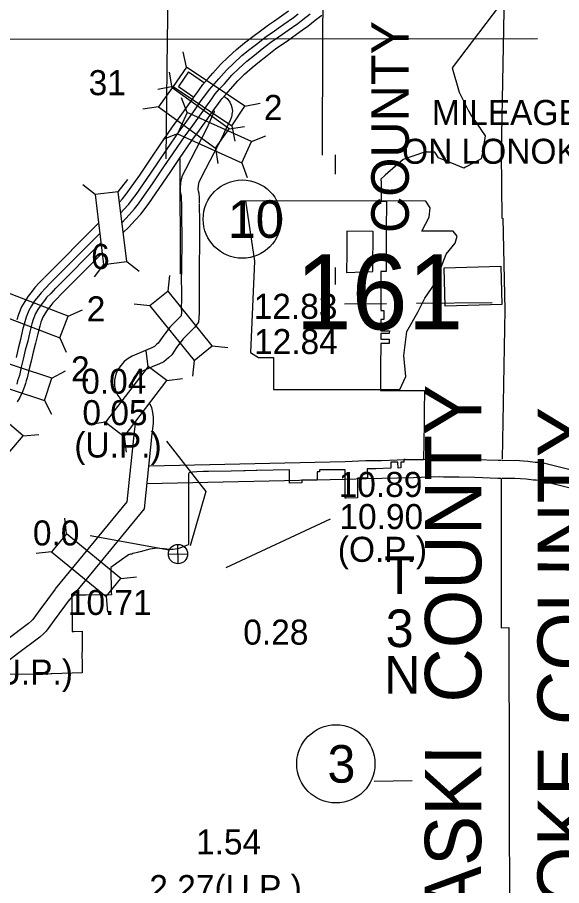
# Model space of a CAD drawing. Extents: x 1127717 to 1741049, y 2026793 to 2244711.
# Drawn here: x 1243581 to 1248173, y 2140586 to 2147909 of the extents above; entities that cross this region are included whole.
import ezdxf

# ---------------------------------------------------------------- set-up
doc = ezdxf.new("R2010")
doc.units = 0
for name, color, linetype in [('10', 7, 'Continuous'), ('15', 7, 'Continuous'), ('2', 7, 'Continuous'), ('20', 7, 'Continuous'), ('21', 7, 'Continuous'), ('25', 7, 'Continuous'), ('27', 7, 'Continuous'), ('30', 7, 'Continuous'), ('5', 7, 'Continuous'), ('58', 7, 'Continuous'), ('6', 7, 'Continuous'), ('Level 30', 7, 'Continuous')]:
    doc.layers.add(name, color=color, linetype=linetype)

msp = doc.modelspace()

# ---------------------------------------------------------------- linework, layer by layer
at = {"layer": '10'}
for points in [[(1245024.4, 2147449.2), (1244939.9, 2147325.2), (1245069.5, 2147236.7)], [(1245024.4, 2147449.2), (1245158.6, 2147357.8)], [(1245324.8, 2147243.9), (1245333.9, 2147236.8), (1245350.9, 2147223.7), (1245374.5, 2147194.8), (1245385.9, 2147169.6), (1245391.2, 2147147.8), (1245394.7, 2147120.3), (1245391.6, 2147092.9), (1245390.1, 2147083.9), (1245387.8, 2147069.8), (1245378.9, 2147047.5), (1245363.6, 2147017.2), (1245338.1, 2146962.1), (1245311.8, 2146904.5), (1245132.7, 2146558.7)], [(1245234.6, 2147123.5), (1245241.4, 2147118.2), (1245242.4, 2147117.4), (1245242, 2147113.4), (1245241.5, 2147110.4), (1245241.1, 2147109.4), (1245227.6, 2147082.9), (1245200.8, 2147024.9), (1245175.4, 2146969.2), (1244998.8, 2146626.3)], [(1244998.8, 2146626.3), (1244974.7, 2146578.6), (1244968.4, 2146563.9), (1244964.3, 2146551.3), (1244960, 2146533.3), (1244954.2, 2146476.3), (1244953.8, 2146456.6), (1244954.9, 2146439.8), (1244956.7, 2146426.6), (1244960.5, 2146412.4), (1244962, 2146405), (1244964.1, 2146377.2), (1244965.9, 2146332.6)], [(1245132.7, 2146558.7), (1245110.7, 2146515.1), (1245108.9, 2146510.8), (1245108.7, 2146510.3), (1245108.2, 2146508.2), (1245104.1, 2146467), (1245103.9, 2146459.7), (1245104.1, 2146455.9), (1245106.5, 2146446.7), (1245110.8, 2146426.1), (1245113.9, 2146385.8), (1245115.7, 2146338.5)], [(1244965.9, 2146332.6), (1244966.5, 2146179), (1244968.4, 2146102.4), (1244968.6, 2146020.3), (1244967.6, 2145940.7), (1244965.7, 2145877.6), (1244964.7, 2145778.9), (1244963.9, 2145695.1), (1244964.4, 2145606.7), (1244964.2, 2145517.3), (1244964.1, 2145468), (1244964.3, 2145419.3), (1244962.4, 2145393.3), (1244961.7, 2145392.5), (1244866.1, 2145296.7)], [(1245115.9, 2146333.3), (1245116.5, 2146181.1), (1245118.4, 2146104.5), (1245118.6, 2146019.6), (1245117.6, 2145937.5), (1245115.7, 2145874.5), (1245114.7, 2145777.4), (1245113.9, 2145694.8), (1245114.4, 2145607), (1245114.2, 2145517), (1245114.1, 2145468), (1245114.3, 2145414.1), (1245108.8, 2145339.5), (1245076, 2145294.6), (1244980.1, 2145198.6)], [(1244265.7, 2146173.8), (1243809.8, 2145715.8)], [(1244276.4, 2146087.1), (1243858.5, 2145667.3)], [(1244286.2, 2146008.3), (1243902.8, 2145623.2)], [(1244296.9, 2145921.6), (1243951.5, 2145574.7)], [(1244866.1, 2145296.7), (1244802.1, 2145210.1), (1244769, 2145160.9), (1244755.9, 2145148.9), (1244736.7, 2145132.3), (1244715.7, 2145123.2), (1244680.2, 2145108.9), (1244550.1, 2145050.5), (1244515, 2145030.5), (1244482.4, 2145006.2), (1244456.6, 2144976.6), (1244429.3, 2144940.4), (1244411.4, 2144898.4), (1244400.1, 2144848.9), (1244400, 2144798.5), (1244411.7, 2144756.9), (1244428.4, 2144721), (1244452.7, 2144686.6), (1244459.6, 2144679.1)], [(1244980.1, 2145198.6), (1244924.7, 2145123.6), (1244883.4, 2145062.3), (1244855.7, 2145037), (1244817.5, 2145003.8), (1244773.4, 2144984.8), (1244739, 2144970.9), (1244618, 2144916.5), (1244597.2, 2144904.7), (1244584.9, 2144895.6), (1244573.1, 2144882), (1244560.1, 2144864.8), (1244554.7, 2144852), (1244550.1, 2144831.9), (1244550.1, 2144819.1), (1244552.9, 2144809), (1244557.3, 2144799.6)], [(1244693.8, 2144655.6), (1244697.7, 2144649.4), (1244712.4, 2144617.5), (1244722.2, 2144576.2), (1244725.9, 2144537.2), (1244726.9, 2144484.7), (1244721.9, 2144442.3), (1244716.4, 2144396.5), (1244649.2, 2143763.3), (1244016.9, 2142992.7)], [(1244576.5, 2144506.7), (1244576.8, 2144492.1), (1244573, 2144460.1), (1244567.3, 2144413.4), (1244504.7, 2143823.8), (1243900.9, 2143087.8)], [(1247664.5, 2144170.7), (1247637.9, 2144170.7), (1247443.6, 2144176.8), (1247311.4, 2144180.4), (1247180.9, 2144181.4), (1247141.5, 2144183.3), (1247047.7, 2144180.5), (1246920, 2144176.1), (1246784.7, 2144173.5), (1246653.7, 2144170.1), (1246521.6, 2144168.1), (1246345.9, 2144161.2), (1244694.8, 2144124.4)], [(1247672.2, 2144173), (1247781.7, 2144173.1), (1247888.2, 2144166.6), (1247950.3, 2144158.9), (1247973, 2144157.1), (1248019.2, 2144151.8), (1248065.5, 2144141.6), (1248438.7, 2144048.5)], [(1247663.1, 2144020.7), (1247635.4, 2144020.7), (1247439.2, 2144026.9), (1247308.7, 2144030.4), (1247176.7, 2144031.4), (1247140.1, 2144033.2), (1247052.5, 2144030.6), (1246924, 2144026.2), (1246788.1, 2144023.6), (1246656.9, 2144020.1), (1246525.7, 2144018.1), (1246350.5, 2144011.3), (1244673.1, 2143973.8)], [(1247671.4, 2144023), (1247777.1, 2144023.1), (1247874.4, 2144017.1), (1247935.2, 2144009.7), (1247958.5, 2144007.8), (1247994.3, 2144003.7), (1248031.1, 2143995.6), (1248402.3, 2143903)], [(1243898.9, 2143085.3), (1243769, 2142912), (1243734.4, 2142862.7), (1243709.9, 2142830.5), (1243698.6, 2142819.4), (1243674.7, 2142797.3), (1243491.4, 2142660.2), (1243211.8, 2142447.8), (1242963, 2142262.3), (1242790.6, 2142134.3), (1242584.6, 2141983.8), (1242522, 2141937.1), (1242493.2, 2141917.6), (1242476.6, 2141902.6), (1242450.7, 2141877.1), (1242424.4, 2141844.8), (1242306.6, 2141708.8), (1242245, 2141634.7), (1242230.2, 2141613.9)], [(1244018.9, 2142995.3), (1243890.4, 2142823.9), (1243855.5, 2142774.2), (1243822.8, 2142731.1), (1243802.2, 2142710.9), (1243771, 2142681.9), (1243581.7, 2142540.4), (1243302, 2142328), (1243052.6, 2142142), (1242879.6, 2142013.5), (1242673.7, 2141863.1), (1242608.9, 2141814.8), (1242585.9, 2141799.2), (1242579.4, 2141793.3), (1242561.8, 2141776), (1242539.3, 2141748.4), (1242421, 2141611.8), (1242363.9, 2141543.1), (1242339.2, 2141508.4), (1242308.1, 2141461.2), (1242275.8, 2141417), (1242253.4, 2141381.2), (1242227.4, 2141356.2)]]:
    msp.add_lwpolyline(points, dxfattribs=at)
at = {"layer": '15'}
for points in [[(1244443.3, 2146351), (1244468.1, 2146379), (1244498.4, 2146416.7), (1244526.1, 2146455.9), (1244613, 2146579.5), (1244708.9, 2146720.8), (1244784.4, 2146832.9), (1244890.6, 2146984.9), (1244953.7, 2147073.3), (1245025.7, 2147172.7), (1245077.2, 2147247), (1245115.6, 2147297.8), (1245146.2, 2147343.6), (1245189.3, 2147392.7), (1245230.1, 2147437.6), (1245295.8, 2147511.1), (1245358.8, 2147573.9), (1245430.3, 2147638.5), (1245498.5, 2147693.9), (1245566.5, 2147746.9), (1245642, 2147804.9), (1245699.3, 2147844.8), (1245742.5, 2147874.5), (1245788.7, 2147908.7), (1245869.4, 2147964.4)], [(1244454.4, 2146261), (1244477.5, 2146285.9), (1244520.7, 2146334.7), (1244553.3, 2146375.3), (1244582.3, 2146416.3), (1244669.5, 2146540.4), (1244765.9, 2146682.3), (1244841.1, 2146794), (1244946.7, 2146945.3), (1245009.5, 2147033.2), (1245081.8, 2147133), (1245132.9, 2147206.6), (1245171.7, 2147257.9), (1245200.9, 2147301.7), (1245240.5, 2147346.9), (1245281.2, 2147391.6), (1245345.7, 2147463.8), (1245406.2, 2147524), (1245475, 2147586.3), (1245541.3, 2147640.2), (1245608.6, 2147692.6), (1245682.6, 2147749.4), (1245738.4, 2147788.2), (1245782.4, 2147818.6), (1245828.7, 2147852.7), (1245910.1, 2147909), (1245949.8, 2147939.9)], [(1244464.4, 2146180), (1244523.8, 2146243.9), (1244568.5, 2146294.4), (1244603.2, 2146337.6), (1244633.4, 2146380.2), (1244721, 2146504.9), (1244817.6, 2146647.3), (1244892.7, 2146758.7), (1244997.8, 2146909.2), (1245060.3, 2146996.7), (1245132.8, 2147096.8), (1245183.6, 2147170), (1245222.6, 2147221.7), (1245250.6, 2147263.6), (1245287.2, 2147305.3), (1245327.6, 2147349.7), (1245391.1, 2147420.8), (1245449.2, 2147478.7), (1245515.7, 2147538.8), (1245580.2, 2147591.3), (1245646.8, 2147643.1), (1245719.4, 2147698.9), (1245774, 2147736.8), (1245818.7, 2147767.7), (1245865, 2147801.8), (1245947.2, 2147858.6), (1245988.2, 2147890.6), (1246051.3, 2147939.4)], [(1244474.8, 2146096.4), (1244519.2, 2146137.9), (1244574.8, 2146197.7), (1244621.1, 2146250.1), (1244658.1, 2146296.2), (1244689.6, 2146340.6), (1244777.5, 2146465.8), (1244874.6, 2146608.8), (1244949.4, 2146719.8), (1245053.9, 2146869.5), (1245116.1, 2146956.5), (1245188.9, 2147057), (1245239.3, 2147129.6), (1245278.7, 2147181.9), (1245305.3, 2147221.6), (1245338.5, 2147259.5), (1245378.7, 2147303.7), (1245441.1, 2147373.6), (1245496.5, 2147428.8), (1245560.5, 2147486.6), (1245623.1, 2147537.5), (1245688.9, 2147588.8), (1245760, 2147643.4), (1245813.1, 2147680.3), (1245858.6, 2147711.7), (1245904.9, 2147745.9), (1245987.9, 2147803.1), (1246030.4, 2147836.3), (1246092.7, 2147884.5), (1246149.8, 2147926.6)], [(1243807.7, 2145713.6), (1243768.5, 2145671.8), (1243728.3, 2145631.8), (1243705.3, 2145600.8), (1243670.5, 2145557.2), (1243642.6, 2145513.4), (1243615.1, 2145468.4), (1243590, 2145403), (1243576.8, 2145359.2)], [(1243857.9, 2145666.6), (1243817.8, 2145623.9), (1243780.4, 2145586.7), (1243759.8, 2145558.9), (1243726.6, 2145517.2), (1243700.9, 2145477), (1243677.1, 2145437.9), (1243655.1, 2145380.7), (1243643, 2145340.5), (1243625.1, 2145272.6), (1243606.9, 2145193.2), (1243586.6, 2145116.6), (1243569.4, 2145039.5)], [(1243903.5, 2145623.8), (1243862.7, 2145580.3), (1243827.8, 2145545.6), (1243809.3, 2145520.8), (1243777.5, 2145480.8), (1243753.9, 2145443.9), (1243733.4, 2145410.2), (1243714.2, 2145360.5), (1243703.1, 2145323.5), (1243685.8, 2145257.7), (1243667.6, 2145178.2), (1243647.4, 2145101.7), (1243630.2, 2145025), (1243613.5, 2144959.3), (1243598.3, 2144887.6), (1243590.9, 2144866.7), (1243583, 2144842.4), (1243574.8, 2144816.3)], [(1243953.6, 2145576.8), (1243912, 2145532.4), (1243879.9, 2145500.5), (1243863.8, 2145478.9), (1243833.5, 2145440.8), (1243812.3, 2145407.6), (1243795.3, 2145379.7), (1243779.3, 2145338.2), (1243769.3, 2145304.9), (1243752.6, 2145241.3), (1243734.4, 2145161.7), (1243714.2, 2145085.4), (1243697, 2145009), (1243680.5, 2144943.7), (1243664.6, 2144868.9), (1243656, 2144844.7), (1243648.5, 2144821.5), (1243640.2, 2144794.9), (1243625, 2144750.8), (1243600.4, 2144703.6), (1243580.4, 2144667.7)]]:
    msp.add_lwpolyline(points, dxfattribs=at)
at = {"layer": '2'}
for points in [[(1247597.6, 2151689.9), (1247594.9, 2150725.5), (1247690.9, 2150725.1), (1247700.5, 2149465), (1247688.4, 2148116.6), (1247661.8, 2146767.3), (1247669.5, 2146213.4)], [(1247677.3, 2146215.7), (1247694.3, 2145442.6), (1247672.5, 2144184.2)], [(1247663.1, 2144020.7), (1247662.8, 2142760.5), (1247726.6, 2142761.9), (1247731.3, 2141494.2), (1247734.4, 2140166.2), (1247725.8, 2138824.4), (1247726.7, 2138603.6)]]:
    msp.add_lwpolyline(points, dxfattribs=at)
at = {"layer": '20'}
for p, q in [((1245006.4, 2147489.9), (1244980.7, 2147619.4)), ((1244886.3, 2147316.1), (1244865.5, 2147446.4)), ((1244896.4, 2147325.3), (1244766.9, 2147299.6)), ((1245013.3, 2147106.5), (1244966.5, 2147230)), ((1245500.2, 2147159.9), (1245629.7, 2147185.6)), ((1244770.2, 2147155.7), (1244639.8, 2147134.9)), ((1245013.3, 2147106.5), (1244932.1, 2146926)), ((1245555, 2146862.8), (1245013.3, 2147106.5)), ((1245367.4, 2146967.7), (1245497.7, 2146988.5)), ((1245390.2, 2146995.2), (1245415.9, 2146865.8)), ((1244932.1, 2146926), (1244808.7, 2146879.1)), ((1244932.1, 2146926), (1245473.8, 2146682.3)), ((1245555, 2146862.8), (1245678.4, 2146909.6)), ((1245473.8, 2146682.3), (1245555, 2146862.8)), ((1245251.2, 2146807.3), (1245272.1, 2146677)), ((1245473.8, 2146682.3), (1245520.6, 2146558.8)), ((1244432.5, 2146438.6), (1244513.7, 2146542.7)), ((1244236, 2146414.3), (1244131.9, 2146495.5)), ((1244308.8, 2145824.8), (1244227.6, 2145720.7)), ((1244505.3, 2145849.1), (1244609.4, 2145767.9)), ((1244852.7, 2145600.8), (1244866.8, 2145732)), ((1244698.5, 2145476.5), (1244567.2, 2145490.7)), ((1244010.3, 2145389.7), (1244130.9, 2145443.3)), ((1243939.1, 2145205), (1243992.7, 2145084.3)), ((1245225.3, 2145138.2), (1245356.6, 2145124.1)), ((1244685.2, 2144965.8), (1244667.7, 2145096.6)), ((1245071.1, 2145014), (1245057, 2144882.7)), ((1243870.5, 2144867), (1243988.1, 2144926.8)), ((1244842.5, 2144845.6), (1244973.4, 2144863.1)), ((1243809.2, 2144678.7), (1243869, 2144561)), ((1244324.5, 2144493.8), (1244193.7, 2144476.3)), ((1243629.9, 2144380.9), (1243761.5, 2144392)), ((1244481.9, 2144373.6), (1244499.3, 2144242.8)), ((1243995.5, 2143553.1), (1243982.5, 2143684.5)), ((1243869.9, 2143400), (1243738.5, 2143387.1)), ((1244454.7, 2143176.3), (1244586.1, 2143189.3)), ((1244329.1, 2143023.3), (1244342.1, 2142891.9))]:
    msp.add_line(p, q, dxfattribs=at)
for points in [[(1245500.2, 2147159.9), (1245006.4, 2147489.9), (1244896.4, 2147325.3), (1245390.2, 2146995.2)], [(1245367.4, 2146967.7), (1244886.3, 2147316.1), (1244770.2, 2147155.7), (1245251.2, 2146807.3)], [(1244505.3, 2145849.1), (1244432.5, 2146438.6), (1244236, 2146414.3), (1244308.8, 2145824.8)], [(1243384.8, 2145418.4), (1243939.1, 2145205), (1244010.3, 2145389.7), (1243456, 2145603.2)], [(1244698.5, 2145476.5), (1245071.1, 2145014), (1245225.3, 2145138.2), (1244852.7, 2145600.8)], [(1243244.4, 2144862.7), (1243809.2, 2144678.7), (1243870.5, 2144867), (1243305.7, 2145051)], [(1244481.9, 2144373.6), (1244842.5, 2144845.6), (1244685.2, 2144965.8), (1244324.5, 2144493.8)], [(1243629.9, 2144380.9), (1243175.9, 2144763.9), (1243048.3, 2144612.5), (1243502.3, 2144229.5)], [(1244454.7, 2143176.3), (1243995.5, 2143553.1), (1243869.9, 2143400), (1244329.1, 2143023.3)]]:
    msp.add_lwpolyline(points, close=True, dxfattribs=at)
at = {"layer": '21'}
msp.add_lwpolyline([(1245505.9, 2146360.6), (1245582, 2145853.1), (1245548.2, 2145083.3), (1245615.9, 2145041), (1245742.7, 2145041), (1245742.7, 2144770.4), (1246808.6, 2144770.4), (1246859.3, 2144880.3), (1246842.4, 2145058), (1246867.8, 2145261), (1246960.8, 2145421.7), (1247020, 2145540.1), (1247104.6, 2145667), (1247155.4, 2145802.3), (1247197.7, 2145912.3), (1247273.8, 2146005.4), (1247290.7, 2146064.6), (1247256.9, 2146106.9), (1246994.7, 2146106.9), (1247053.9, 2146225.3), (1247062.3, 2146301.4), (1247027.3, 2146359.9)], close=True, dxfattribs=at)
at = {"layer": '25'}
for p, q in [((1244937.9, 2143301.3), (1244934.1, 2143464.1)), ((1244854.7, 2143380.8), (1245017.4, 2143384.6))]:
    msp.add_line(p, q, dxfattribs=at)
msp.add_lwpolyline([(1244861, 2143415.3), (1244194.1, 2143536.6)], dxfattribs=at)
msp.add_circle((1244936, 2143382.7), 81.4, dxfattribs=at)
at = {"layer": '27'}
for centre in [(1245478.1, 2146207.8), (1246268.2, 2141612.9)]:
    msp.add_circle(centre, 330, dxfattribs=at)
at = {"layer": '30'}
for q in [(1247968.3, 2147730.6), (1247923.9, 2147730.5)]:
    msp.add_line((1238326.3, 2147717.7), q, dxfattribs=at)
at = {"layer": '5'}
for points in [[(1244848.3, 2147726.4), (1244851.9, 2148062), (1244842.5, 2149408.9), (1244847.7, 2150774.7), (1244852.7, 2151676.2)], [(1246159.2, 2147728.1), (1246160.6, 2148082.1), (1246169.1, 2149411.4), (1246171.1, 2150787.1), (1246168.3, 2151684.2)], [(1244837.3, 2146716), (1244848.3, 2147726.4)], [(1246155.2, 2146747.9), (1246159.2, 2147728.1)], [(1246263.7, 2146586.1), (1246263.7, 2146749.3)], [(1244956.5, 2145744.6), (1244954.2, 2146717.6)], [(1246263.6, 2145656.7), (1246263.6, 2145798.6)], [(1246340.1, 2145494.1), (1246694.7, 2145496.9)], [(1246948.3, 2145498.9), (1247586, 2145503.9)], [(1246590.3, 2141467.9), (1246913.2, 2141471.3)]]:
    msp.add_lwpolyline(points, dxfattribs=at)
at = {"layer": '58'}
msp.add_line((1245343.3, 2143270.1), (1246222.9, 2143678.5), dxfattribs=at)
msp.add_lwpolyline([(1244839.9, 2144333.4), (1245170.6, 2143911), (1245038.4, 2143453)], dxfattribs=at)
at = {"layer": '6'}
for points in [[(1247700.8, 2148083.3), (1247248.4, 2147482.3), (1247307.4, 2147279.6), (1247389.1, 2147114.3), (1247410.8, 2147082.4), (1247446.3, 2147030.1), (1247480.1, 2146980.3), (1247481.9, 2146977.6), (1247492.2, 2146962.3), (1247527.4, 2146910.4), (1247510.2, 2146807), (1247504, 2146769.6), (1247494.3, 2146716), (1247437.6, 2146685.5), (1247363, 2146645.4), (1247349, 2146637.8), (1247279.9, 2146665.6), (1247132.8, 2146724.6), (1247103.8, 2146771.9), (1247016.9, 2146772.3), (1246835.1, 2146711.6), (1246684.5, 2146577.9), (1246646.4, 2146544), (1246648.3, 2146535.8), (1246648.3, 2146535.8), (1246649.6, 2146527.5), (1246649.6, 2146527.5), (1246650.4, 2146519.2), (1246650.4, 2146519.2), (1246650.7, 2146510.8), (1246650.4, 2146404.6), (1246650.4, 2146403.2), (1246650.4, 2146401.9), (1246650.4, 2146401.6), (1246650.3, 2146360), (1246694.7, 2146358.5), (1246693.8, 2146112.5), (1246693.8, 2146111.2), (1246693.8, 2146109.9), (1246693.8, 2146103.7), (1246692.6, 2145765.5), (1246648.7, 2145765.6), (1246647.9, 2145437.7), (1246671.4, 2145437.8), (1246671.4, 2145434.1), (1246671.5, 2145431.3), (1246671.5, 2145428.5), (1246671.6, 2145424.5), (1246671.5, 2145394.5), (1246671.5, 2145391), (1246671.4, 2145361.4), (1246646.7, 2145361.4), (1246646.8, 2145342.4), (1246646.8, 2145321.8), (1246646.8, 2145308.6), (1246647, 2145295.5), (1246647.1, 2145281.6), (1246647.1, 2145266.3), (1246655.1, 2145266.4), (1246656.3, 2145266.4), (1246668.1, 2145266.4), (1246673.7, 2145266.4), (1246697.3, 2145266.4), (1246697.7, 2145266.4), (1246699.4, 2145266.4), (1246719.2, 2145266.3), (1246719.1, 2145241.4), (1246715.2, 2145241.4), (1246647, 2145241.4), (1246647, 2145222), (1246646.9, 2145210.8), (1246646.9, 2145210.7), (1246646.9, 2145201.1), (1246646.8, 2145193.6), (1246651.1, 2145193.6), (1246651.2, 2145193.6), (1246714.3, 2145193.6), (1246719, 2145193.7), (1246719, 2145158.5), (1246646.7, 2145158.7), (1246646.6, 2145124.9), (1246646.5, 2145102.5), (1246646.3, 2145096.1), (1246646.3, 2145094), (1246646.2, 2145091.7), (1246644.7, 2145026.4), (1246643.6, 2144980.8), (1246646, 2144928.7), (1246645.6, 2144761.6), (1247016.2, 2144760.9), (1247013.6, 2144588.8), (1247012, 2144479.5), (1247007.4, 2144177.9), (1246856.2, 2144178.2), (1246851.7, 2144178.8)], [(1246851.7, 2144178.8), (1246848.7, 2144179.2), (1246846, 2144179.6), (1246842.6, 2144180), (1246842.1, 2144156.3), (1246815.9, 2144156.4), (1246816.8, 2144108.7), (1246792.5, 2144107.8), (1246791.6, 2144156.4), (1246783.7, 2144156.4), (1246773.6, 2144156.5), (1246732.3, 2144156.6), (1246732.2, 2144105.9), (1246604.2, 2144102.3), (1246580.6, 2144101.6), (1246574.7, 2144101.5), (1246570.2, 2144101.3), (1246549.6, 2144100.8), (1246539.5, 2144100.5), (1246531.4, 2144100.2), (1246531.7, 2144095.1), (1246531.8, 2144092.9), (1246531.9, 2144090.6), (1246535, 2144023.9), (1246449.5, 2144022.9), (1246450.5, 2143858.7), (1246450.5, 2143855.4), (1246355.6, 2143854.6), (1246352.5, 2143854.5), (1246349.8, 2143854.5), (1246346.5, 2143854.5), (1246347.1, 2144083.6), (1246347.1, 2144086.9), (1246347.1, 2144089.2), (1246347.1, 2144092), (1246268.1, 2144092.3), (1246265.2, 2144092.4), (1246262.8, 2144092.4), (1246137.2, 2144092.9), (1246129, 2144092.9), (1246129, 2144092.7), (1246129, 2144088.9), (1246129, 2144086.6), (1246129, 2144084.2), (1246129.1, 2144075.2), (1246111.3, 2144074.8), (1246110.5, 2144006.3), (1246080.6, 2144006.1), (1246065.7, 2144005.9), (1245980.7, 2144005.1), (1245980.6, 2143982.2), (1245876, 2143981.3), (1245876.7, 2144081.7), (1245876.7, 2144083.7), (1245876.7, 2144086.1), (1245876.8, 2144091.8), (1245601.9, 2144086.7), (1245598.8, 2144086.6), (1245595.7, 2144086.6), (1245504.1, 2144084.9), (1245500.7, 2144084.8), (1245498.5, 2144084.8), (1245497.1, 2144084.7), (1245495.1, 2144084.7), (1245491.6, 2144084.6), (1245384.7, 2144082.6), (1245192.7, 2144079.1), (1245190.5, 2144079), (1245164.9, 2144078.2), (1245156.5, 2144077.9), (1245153.6, 2144077.8), (1245151, 2144077.8), (1245095.1, 2144075.9), (1245059.3, 2144071.9), (1245038.6, 2144069.5), (1245034.7, 2144069.1), (1245031.2, 2144068.7), (1245029.8, 2144068.5), (1245027.6, 2144064), (1245027.5, 2144063.7), (1245025.9, 2144060.4), (1245025.1, 2144058.8), (1245025.1, 2144057.6), (1245024.7, 2143484.3), (1245024.7, 2143462.1), (1245022.2, 2143461.1), (1244965, 2143437.8), (1244933.4, 2143426.1), (1244932.2, 2143426), (1244894.5, 2143421.7), (1244866.8, 2143421.8), (1244818.7, 2143425.3), (1244780.5, 2143429.1), (1244757.7, 2143431.3), (1244739.3, 2143430.7), (1244702.4, 2143423.5), (1244698.9, 2143422.6), (1244618.2, 2143401.8), (1244615.9, 2143401.2), (1244602.2, 2143397.5)], [(1244602.2, 2143397.5), (1244594.6, 2143395.8), (1244556.9, 2143386.1), (1244556.3, 2143385.9), (1244545.5, 2143382.5), (1244536.2, 2143380.7), (1244518.9, 2143376.1), (1244507.5, 2143368.1), (1244459.2, 2143334.1), (1244370.5, 2143269.3), (1244373.4, 2143061.7), (1244373.7, 2143039.8), (1244159.1, 2143036.9), (1244099.8, 2143036.1), (1244039.5, 2143035.3), (1244040.8, 2142941.9), (1244040.9, 2142937.6), (1244040.9, 2142932.9), (1244041.3, 2142901.3), (1244041.4, 2142897), (1244042.1, 2142844.3), (1244042.1, 2142842.1), (1244043.7, 2142728.6), (1244058.3, 2142729.1), (1244127.2, 2142731.2), (1244127.1, 2142720), (1244127.1, 2142718.7), (1244127.1, 2142717.4), (1244126.6, 2142627.8), (1244126.4, 2142603.9), (1244125.8, 2142504), (1244127.5, 2142492.2), (1244127.8, 2142489.4), (1244128.2, 2142486.6), (1244128.2, 2142486.5), (1244128.2, 2142471.4), (1244128.2, 2142471.1), (1244128.1, 2142459.4), (1244128.1, 2142459.2), (1244127.7, 2142380.4), (1243872.5, 2142371.8), (1243866.9, 2142371.6), (1243831.8, 2142370.5), (1243831.4, 2142365.8), (1243829.4, 2142365.8), (1243828, 2142365.8), (1243826.4, 2142365.9), (1243503, 2142369.1)]]:
    msp.add_lwpolyline(points, dxfattribs=at)
for points in [[(1246358.9, 2145758.6), (1246360, 2145758.6), (1246497.9, 2145763.2), (1246578.9, 2145765.8), (1246579.2, 2145795.9), (1246582.1, 2146087.9), (1246582.2, 2146104), (1246360.1, 2146104.6), (1246359.5, 2145937.5), (1246359.5, 2145919.1)], [(1247190.6, 2145473.1), (1247180.9, 2145796.2), (1247658.6, 2145810.5), (1247668.3, 2145487.4)]]:
    msp.add_lwpolyline(points, close=True, dxfattribs=at)

# ---------------------------------------------------------------- texts
at = {"layer": '20'}
for p in [(1245660.6, 2147044), (1244165.8, 2145345.1), (1244033.2, 2144838.3)]:
    msp.add_text('2', height=211.2, dxfattribs=at).set_placement(p)
at = {"layer": '21'}
msp.add_text('161', height=633.6, dxfattribs=at).set_placement((1245930.3, 2145276.7))
at = {"layer": '25'}
msp.add_text('0.0', height=211.2, dxfattribs=at).set_placement((1243711.8, 2143454.9))
at = {"layer": '27'}
for s, p in [('10', (1245356, 2146049.4)), ('3', (1246197.3, 2141454.5))]:
    msp.add_text(s, height=316.8, dxfattribs=at).set_placement(p)
at = {"layer": '30'}
msp.add_text('COUNTY', height=316.8, rotation=90, dxfattribs=at).set_placement((1246883.5, 2146090.6))
for s, height, p in [('MILEAGE CARRIED', 211.2, (1247078.9, 2147001.1)), ('ON LONOKE CO. LOG', 211.2, (1246826.7, 2146674.2)), ('T', 316.8, (1246676.9, 2143046.7)), ('3', 316.8, (1246688.4, 2142598.2)), ('N', 316.8, (1246675.5, 2142206.3))]:
    msp.add_text(s, height=height, dxfattribs=at).set_placement(p)
at = {"layer": '5'}
for s, p in [('31', (1244182.2, 2147252.8)), ('6', (1244202.8, 2145786.9))]:
    msp.add_text(s, height=211.2, dxfattribs=at).set_placement(p)
at = {"layer": '58'}
for s, p in [('12.83', (1245574.3, 2145366.4)), ('12.84', (1245577.5, 2145068.9)), ('0.04', (1244119.4, 2144734.2)), ('0.05', (1244129.6, 2144469.5)), ('(U.P.)', (1244061.1, 2144196.7)), ('10.89', (1246291.6, 2143864)), ('10.90', (1246297.6, 2143593.2)), ('(O.P.)', (1246284.4, 2143316.9)), ('10.71', (1244006.5, 2142868.9)), ('0.28', (1245486.7, 2142618.4)), ('9.81(U.P.)', (1242762.5, 2142281.5)), ('1.54', (1245087.9, 2140848.6)), ('2.27(U.P.)', (1244693.8, 2140463.6))]:
    msp.add_text(s, height=211.2, dxfattribs=at).set_placement(p)
at = {"layer": 'Level 30'}
for s, p in [('PULASKI  COUNTY', (1247492.9, 2139091.4)), ('LONOKE COUNTY', (1248443.3, 2139114.5))]:
    msp.add_text(s, height=475.199, rotation=89.9667, dxfattribs=at).set_placement(p)

doc.saveas('drawing.dxf')
